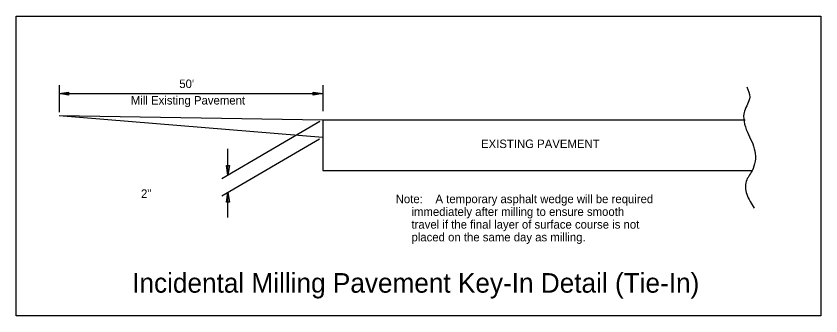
# Model space of a CAD drawing. Extents: x 2111095 to 2115970, y 670428 to 672393.
# Drawn here: x 2112559 to 2113279, y 670752 to 671021 of the extents above; entities that cross this region are included whole.
import ezdxf

# ---------------------------------------------------------------- set-up
doc = ezdxf.new("R2010")
doc.units = 0
for name, color, linetype in [('Old_Level_1', 7, 'Continuous'), ('Old_Level_11', 7, 'Continuous'), ('Old_Level_19', 7, 'Continuous'), ('Old_Level_3', 7, 'Continuous'), ('Old_Level_60', 7, 'Continuous')]:
    doc.layers.add(name, color=color, linetype=linetype)

msp = doc.modelspace()

# ---------------------------------------------------------------- linework, layer by layer
at = {"layer": 'Old_Level_1'}
for p, q in [((2112597.68, 670958.71), (2112597.68, 670934.37)), ((2112833.59, 670958.71), (2112833.59, 670935.31)), ((2112597.68, 670951.06), (2112833.59, 670951.06)), ((2112597.68, 670931.58), (2112833.59, 670927.77)), ((2112830.88, 670926.19), (2112743.31, 670874.95)), ((2112830.54, 670910.38), (2112743.31, 670859.34)), ((2112748.76, 670878.14), (2112748.76, 670901.71)), ((2112748.76, 670840.17), (2112748.76, 670862.53))]:
    msp.add_line(p, q, dxfattribs=at)
msp.add_spline([(2113212.82, 670957.25), (2113215.42, 670947.9), (2113210.74, 670935.42), (2113213.34, 670916.72), (2113220.09, 670899.57), (2113217.5, 670881.9), (2113212.3, 670872.55), (2113212.82, 670861.11), (2113219.57, 670848.64)], degree=3, dxfattribs=at)
at = {"layer": 'Old_Level_11'}
for points in [[(2112606.2, 670949.64), (2112597.68, 670951.06), (2112606.2, 670952.48)], [(2112825.06, 670952.48), (2112833.59, 670951.06), (2112825.06, 670949.64)], [(2112750.18, 670886.66), (2112748.76, 670878.14), (2112747.34, 670886.66)], [(2112747.34, 670854), (2112748.76, 670862.53), (2112750.18, 670854)]]:
    msp.add_lwpolyline(points, close=True, dxfattribs=at)
at = {"layer": 'Old_Level_19'}
msp.add_lwpolyline([(2112559.24, 671020.53), (2113279.13, 671020.53), (2113279.13, 670752.06), (2112559.24, 670752.06)], close=True, dxfattribs=at)
at = {"layer": 'Old_Level_60'}
for p, q in [((2112597.68, 670931.58), (2112833.59, 670912.16)), ((2112833.59, 670927.77), (2112833.59, 670882.27)), ((2112833.59, 670927.77), (2113211.25, 670927.77)), ((2112833.59, 670882.27), (2113217.62, 670882.27))]:
    msp.add_line(p, q, dxfattribs=at)

# ---------------------------------------------------------------- texts
at = {"layer": 'Old_Level_1'}
for s, p in [('Mill Existing Pavement', (2112661.89, 670941.33)), ('   Note:    A temporary asphalt wedge will be required', (2112890.31, 670853.01)), ('        immediately after milling to ensure smooth', (2112890.31, 670841.62)), ('        travel if the final layer of surface course is not', (2112890.31, 670830.22)), ('        placed on the same day as milling.', (2112890.31, 670818.83))]:
    msp.add_text(s, height=7.5963, dxfattribs=at).set_placement(p)
at = {"layer": 'Old_Level_3'}
for s, height, p in [("50'", 7.596, (2112705.22, 670956.1)), ('EXISTING PAVEMENT', 7.5963, (2112975.1, 670902.36)), ('             2"', 7.5963, (2112634.29, 670857.75)), ('Incidental Milling Pavement Key-In Detail (Tie-In)', 17.5007, (2112663.1, 670772.86))]:
    msp.add_text(s, height=height, dxfattribs=at).set_placement(p)

doc.saveas('drawing.dxf')
